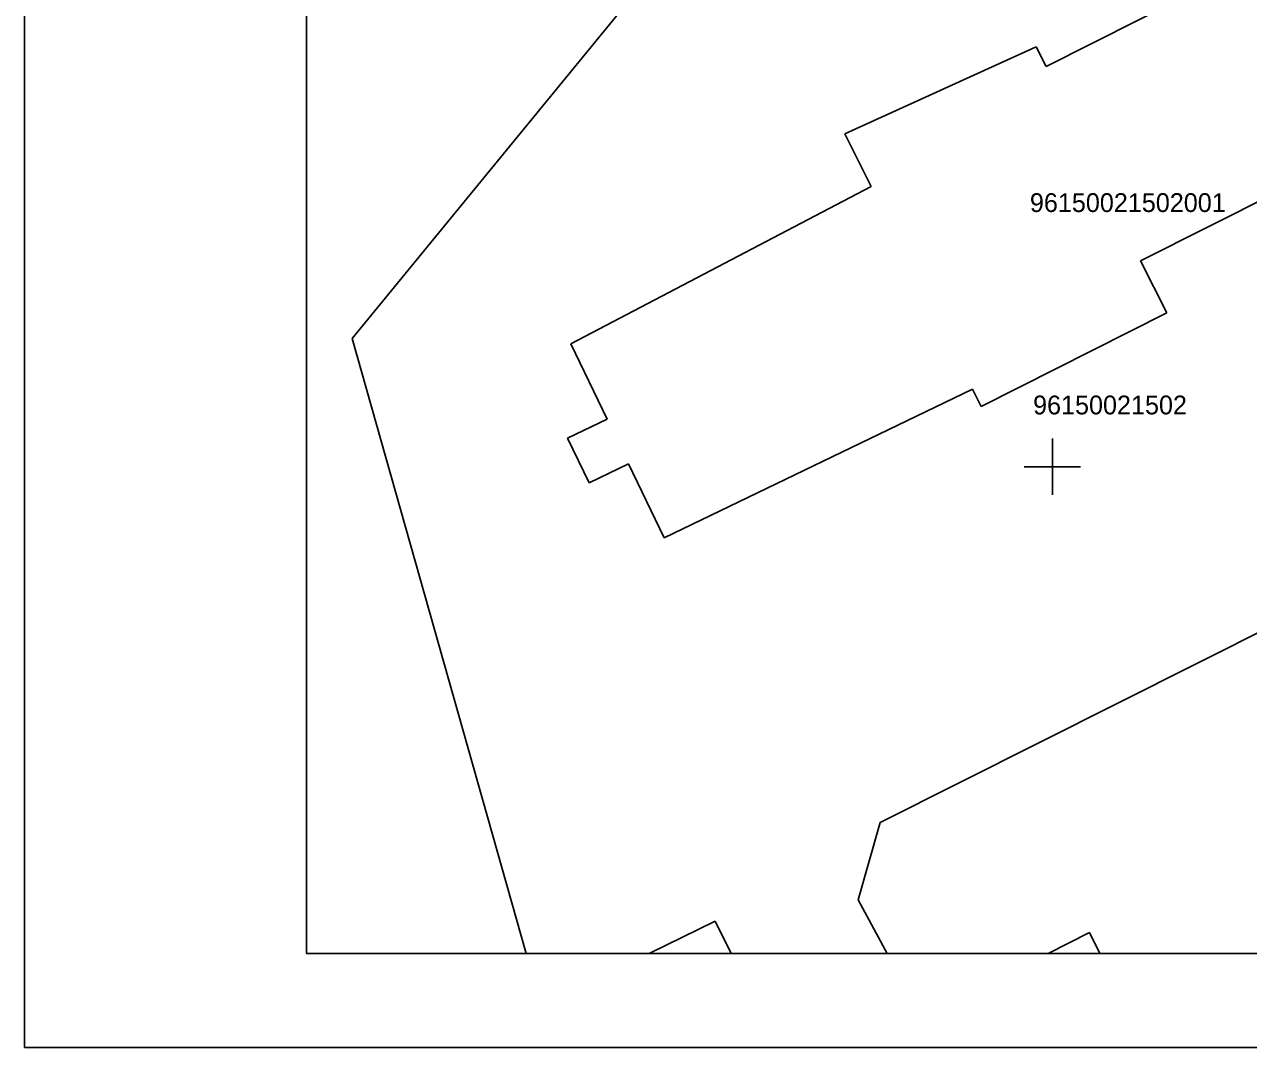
# Model space of a CAD drawing. Extents: x 578395 to 578590, y 418519 to 418816.
# Drawn here: x 578395.4 to 578460.4, y 418519.1 to 418573.5 of the extents above; entities that cross this region are included whole.
import ezdxf

# ---------------------------------------------------------------- set-up
doc = ezdxf.new("R2010")
doc.units = 0
for name, color, linetype in [('BUVE_EKAS_UZMR_####_#', 7, 'Continuous'), ('BUVE_EKAS_UZMR_TKST_#', 7, 'Continuous'), ('GEOD_ELEM_####_####_#', 7, 'Continuous'), ('RAMI_PLAN_####_TKST_#', 7, 'Continuous'), ('ROBZ_UZMR_####_####_#', 7, 'Continuous'), ('ROBZ_UZMR_####_TKST_#', 7, 'Continuous')]:
    doc.layers.add(name, color=color, linetype=linetype)

msp = doc.modelspace()

# ---------------------------------------------------------------- linework, layer by layer
at = {"layer": 'BUVE_EKAS_UZMR_####_#'}
for p, q in [((578449.667, 418571.286), (578468.65, 418580.87)), ((578438.958, 418567.695), (578449.14, 418572.33)), ((578449.14, 418572.33), (578449.667, 418571.286)), ((578473.83, 418570.61), (578454.685, 418560.944)), ((578440.366, 418564.903), (578438.958, 418567.695)), ((578424.391, 418556.529), (578440.366, 418564.903)), ((578454.685, 418560.944), (578456.08, 418558.18)), ((578456.08, 418558.18), (578446.206, 418553.197)), ((578426.32, 418552.531), (578424.391, 418556.529)), ((578445.758, 418554.125), (578429.366, 418546.217)), ((578446.206, 418553.197), (578445.758, 418554.125)), ((578424.222, 418551.518), (578426.32, 418552.531)), ((578425.369, 418549.141), (578424.222, 418551.518)), ((578427.467, 418550.153), (578425.369, 418549.141)), ((578429.366, 418546.217), (578427.467, 418550.153)), ((578428.558, 418524.111), (578432.07, 418525.83)), ((578432.07, 418525.83), (578432.927, 418524.111)), ((578449.773, 418524.111), (578451.97, 418525.22)), ((578451.97, 418525.22), (578452.524, 418524.111))]:
    msp.add_line(p, q, dxfattribs=at)
at = {"layer": 'GEOD_ELEM_####_####_#'}
for p, q in [((578450, 418551.5), (578450, 418550)), ((578448.5, 418550), (578450, 418550)), ((578450, 418550), (578450, 418548.5)), ((578450, 418550), (578451.5, 418550))]:
    msp.add_line(p, q, dxfattribs=at)
at = {"layer": 'RAMI_PLAN_####_TKST_#'}
for p, q in [((578395.351, 418519.111), (578395.351, 418667.611)), ((578590.351, 418519.111), (578395.351, 418519.111))]:
    msp.add_line(p, q, dxfattribs=at)
msp.add_lwpolyline([(578410.351, 418811.111), (578410.351, 418524.111), (578585.351, 418524.111), (578585.351, 418811.111)], close=True, dxfattribs=at)
at = {"layer": 'ROBZ_UZMR_####_####_#'}
for p, q in [((578412.77, 418556.81), (578429.74, 418577.54)), ((578422.027, 418524.111), (578412.77, 418556.81)), ((578440.85, 418531.07), (578491.621, 418556.597)), ((578439.67, 418526.96), (578440.85, 418531.07)), ((578441.209, 418524.111), (578439.67, 418526.96))]:
    msp.add_line(p, q, dxfattribs=at)

# ---------------------------------------------------------------- texts
at = {"layer": 'BUVE_EKAS_UZMR_TKST_#'}
msp.add_text('96150021502001', height=1, dxfattribs=at).set_placement((578448.803, 418563.543))
at = {"layer": 'ROBZ_UZMR_####_TKST_#'}
msp.add_text('96150021502', height=1, dxfattribs=at).set_placement((578448.971, 418552.781))

doc.saveas('drawing.dxf')
